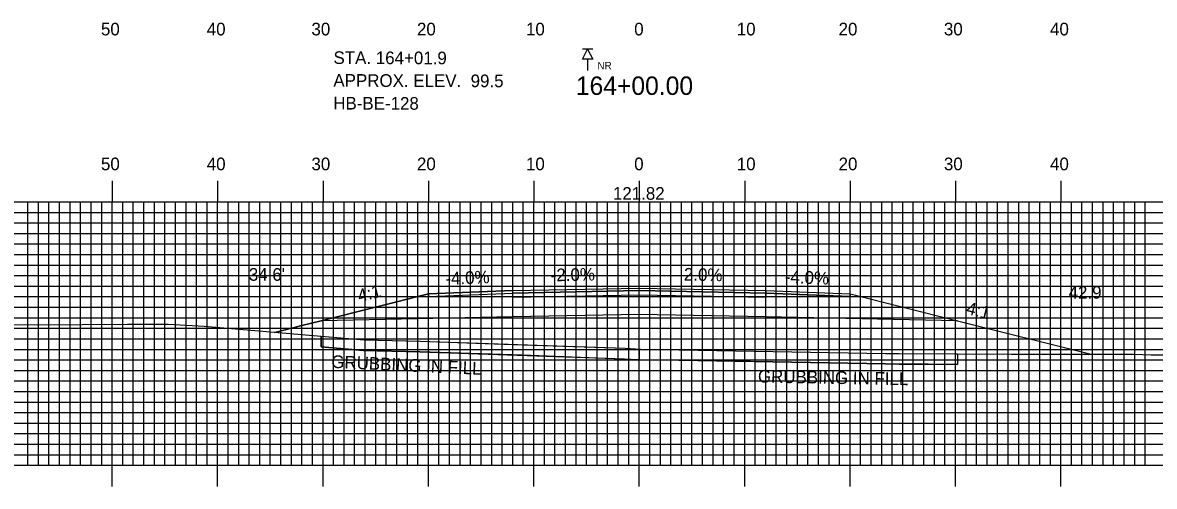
# Model space of a CAD drawing. Extents: x 1780680 to 1781023, y 442591 to 442811.
# Drawn here: x 1780786.9 to 1780894.2, y 442696.7 to 442740.7 of the extents above; entities that cross this region are included whole.
import ezdxf

# ---------------------------------------------------------------- set-up
doc = ezdxf.new("R2010")
doc.units = 0
for name, color, linetype in [('ANNOTATION', 7, 'Continuous'), ('BORING - NO REFUSAL', 7, 'Continuous'), ('D_Roadway_Centerline', 7, 'Continuous'), ('D_Roadway_Centerline_Text', 7, 'Continuous'), ('D_Roadway_Edge_Shoulder', 7, 'Continuous'), ('D_Roadway_Edge_TW', 7, 'Continuous'), ('D_Roadway_Pavement', 7, 'Continuous'), ('D_Roadway_SlopeLines', 7, 'Continuous'), ('D_Roadway_SubGrade', 7, 'Continuous'), ('D_Text_Standard', 7, 'Continuous'), ('GRUBBING IN FILL', 7, 'Continuous'), ('H_V ANNOTATION', 7, 'Continuous'), ('MAJOR', 7, 'Continuous'), ('MINOR', 7, 'Continuous'), ('S_Roadway_Centerline', 7, 'Continuous')]:
    doc.layers.add(name, color=color, linetype=linetype)

msp = doc.modelspace()

# ---------------------------------------------------------------- linework, layer by layer
at = {"layer": 'BORING - NO REFUSAL'}
for p, q in [((1780840.96, 442738.17), (1780840, 442738.17)), ((1780840.48, 442737.21), (1780840.48, 442736.15))]:
    msp.add_line(p, q, dxfattribs=at)
msp.add_lwpolyline([(1780840.48, 442738.17), (1780840.96, 442737.21), (1780840, 442737.21)], close=True, dxfattribs=at)
at = {"layer": 'D_Roadway_Centerline'}
msp.add_lwpolyline([(1780810.81, 442711.28), (1780813.38, 442711.93), (1780815.21, 442712.38), (1780825.38, 442714.93), (1780833.38, 442715.25), (1780845.38, 442715.49), (1780857.38, 442715.25), (1780865.38, 442714.93), (1780875.56, 442712.38), (1780888.25, 442709.21)], dxfattribs=at)
at = {"layer": 'D_Roadway_Edge_Shoulder'}
for points in [[(1780833.38, 442715.25), (1780825.38, 442714.93), (1780825.38, 442714.68), (1780833.38, 442715)], [(1780857.38, 442715.25), (1780865.38, 442714.93), (1780865.38, 442714.68), (1780857.38, 442715)]]:
    msp.add_lwpolyline(points, close=True, dxfattribs=at)
at = {"layer": 'D_Roadway_Edge_TW'}
msp.add_lwpolyline([(1780833.38, 442715), (1780833.38, 442715.25), (1780845.38, 442715.49), (1780857.38, 442715.25), (1780857.38, 442715), (1780845.38, 442715.24)], close=True, dxfattribs=at)
at = {"layer": 'D_Roadway_Pavement'}
msp.add_lwpolyline([(1780833.38, 442714.58), (1780833.38, 442715), (1780845.38, 442715.24), (1780857.38, 442715), (1780857.38, 442714.58), (1780845.38, 442714.82)], close=True, dxfattribs=at)
at = {"layer": 'D_Roadway_SlopeLines'}
for points in [[(1780825.38, 442714.93), (1780815.21, 442712.38), (1780813.38, 442711.93), (1780810.81, 442711.28)], [(1780865.38, 442714.93), (1780875.56, 442712.38), (1780888.25, 442709.21)]]:
    msp.add_lwpolyline(points, dxfattribs=at)
at = {"layer": 'D_Roadway_SubGrade'}
msp.add_lwpolyline([(1780833.38, 442712.75), (1780815.21, 442712.38), (1780825.38, 442714.93), (1780825.38, 442714.68), (1780833.38, 442715), (1780845.38, 442715.24), (1780857.38, 442715), (1780865.38, 442714.68), (1780865.38, 442714.93), (1780875.56, 442712.38), (1780857.38, 442712.75), (1780845.38, 442712.99)], close=True, dxfattribs=at)
at = {"layer": 'GRUBBING IN FILL'}
for p, q in [((1780815.21, 442710.91), (1780815.21, 442709.91)), ((1780815.21, 442710.91), (1780815.21, 442709.91)), ((1780875.56, 442709.24), (1780875.56, 442708.24)), ((1780875.56, 442709.24), (1780875.56, 442708.24))]:
    msp.add_line(p, q, dxfattribs=at)
for points in [[(1780815.21, 442710.91), (1780819.27, 442710.56), (1780824.58, 442710.43), (1780834.31, 442710.11), (1780844.04, 442709.78), (1780845.38, 442709.69), (1780845.38, 442708.68), (1780834.27, 442709.11), (1780824.55, 442709.43), (1780819.21, 442709.56), (1780815.21, 442709.91)], [(1780815.21, 442710.91), (1780819.27, 442710.56), (1780824.58, 442710.43), (1780834.31, 442710.11), (1780844.04, 442709.78), (1780845.38, 442709.69), (1780845.38, 442708.68), (1780834.27, 442709.11), (1780824.55, 442709.43), (1780819.21, 442709.56), (1780815.21, 442709.91)], [(1780845.38, 442709.69), (1780847.39, 442709.67), (1780858.07, 442709.48), (1780868.74, 442709.29), (1780875.56, 442709.24), (1780875.56, 442708.24), (1780872.8, 442708.26), (1780868.73, 442708.29), (1780858.05, 442708.48), (1780845.38, 442708.68)], [(1780845.38, 442709.69), (1780847.39, 442709.67), (1780858.07, 442709.48), (1780868.74, 442709.29), (1780875.56, 442709.24), (1780875.56, 442708.24), (1780872.8, 442708.26), (1780868.73, 442708.29), (1780858.05, 442708.48), (1780845.38, 442708.68)]]:
    msp.add_lwpolyline(points, close=True, dxfattribs=at)
msp.add_lwpolyline([(1780815.21, 442709.91), (1780819.21, 442709.56), (1780824.55, 442709.43), (1780843.99, 442708.78), (1780845.49, 442708.68), (1780847.37, 442708.67), (1780868.73, 442708.29), (1780870.05, 442708.27), (1780875.56, 442708.24)], dxfattribs=at)
msp.add_lwpolyline([(1780815.21, 442709.91), (1780819.21, 442709.56), (1780824.55, 442709.43), (1780843.99, 442708.78), (1780845.49, 442708.68), (1780847.37, 442708.67), (1780868.73, 442708.29), (1780870.05, 442708.27), (1780875.56, 442708.24)], dxfattribs=at)
at = {"layer": 'MAJOR'}
for p, q in [((1780795.38, 442725.67), (1780795.38, 442723.67)), ((1780805.38, 442725.67), (1780805.38, 442723.67)), ((1780815.38, 442725.67), (1780815.38, 442723.67)), ((1780825.38, 442725.67), (1780825.38, 442723.67)), ((1780835.38, 442725.67), (1780835.38, 442723.67)), ((1780845.38, 442725.67), (1780845.38, 442723.67)), ((1780855.38, 442725.67), (1780855.38, 442723.67)), ((1780865.38, 442725.67), (1780865.38, 442723.67)), ((1780875.38, 442725.67), (1780875.38, 442723.67)), ((1780885.38, 442725.67), (1780885.38, 442723.67)), ((1780705.38, 442723.67), (1780985.38, 442723.67)), ((1780705.38, 442723.67), (1780985.38, 442723.67)), ((1780795.38, 442698.67), (1780795.38, 442723.67)), ((1780805.38, 442698.67), (1780805.38, 442723.67)), ((1780815.38, 442698.67), (1780815.38, 442723.67)), ((1780825.38, 442698.67), (1780825.38, 442723.67)), ((1780835.38, 442698.67), (1780835.38, 442723.67)), ((1780845.38, 442698.67), (1780845.38, 442723.67)), ((1780855.38, 442698.67), (1780855.38, 442723.67)), ((1780865.38, 442698.67), (1780865.38, 442723.67)), ((1780875.38, 442698.67), (1780875.38, 442723.67)), ((1780885.38, 442698.67), (1780885.38, 442723.67)), ((1780705.38, 442718.67), (1780985.38, 442718.67)), ((1780705.38, 442713.67), (1780985.38, 442713.67)), ((1780705.38, 442708.67), (1780985.38, 442708.67)), ((1780705.38, 442703.67), (1780985.38, 442703.67)), ((1780705.38, 442698.67), (1780985.38, 442698.67)), ((1780705.38, 442698.67), (1780985.38, 442698.67)), ((1780795.38, 442696.66), (1780795.38, 442698.67)), ((1780805.38, 442696.66), (1780805.38, 442698.67)), ((1780815.38, 442696.66), (1780815.38, 442698.67)), ((1780825.38, 442696.66), (1780825.38, 442698.67)), ((1780835.38, 442696.66), (1780835.38, 442698.67)), ((1780845.38, 442696.66), (1780845.38, 442698.67)), ((1780855.38, 442696.66), (1780855.38, 442698.67)), ((1780865.38, 442696.66), (1780865.38, 442698.67)), ((1780875.38, 442696.66), (1780875.38, 442698.67)), ((1780885.38, 442696.66), (1780885.38, 442698.67))]:
    msp.add_line(p, q, dxfattribs=at)
at = {"layer": 'MINOR'}
for p, q in [((1780787.38, 442698.67), (1780787.38, 442723.67)), ((1780788.38, 442698.67), (1780788.38, 442723.67)), ((1780789.38, 442698.67), (1780789.38, 442723.67)), ((1780790.38, 442698.67), (1780790.38, 442723.67)), ((1780791.38, 442698.67), (1780791.38, 442723.67)), ((1780792.38, 442698.67), (1780792.38, 442723.67)), ((1780793.38, 442698.67), (1780793.38, 442723.67)), ((1780794.38, 442698.67), (1780794.38, 442723.67)), ((1780796.38, 442698.67), (1780796.38, 442723.67)), ((1780797.38, 442698.67), (1780797.38, 442723.67)), ((1780798.38, 442698.67), (1780798.38, 442723.67)), ((1780799.38, 442698.67), (1780799.38, 442723.67)), ((1780800.38, 442698.67), (1780800.38, 442723.67)), ((1780801.38, 442698.67), (1780801.38, 442723.67)), ((1780802.38, 442698.67), (1780802.38, 442723.67)), ((1780803.38, 442698.67), (1780803.38, 442723.67)), ((1780804.38, 442698.67), (1780804.38, 442723.67)), ((1780806.38, 442698.67), (1780806.38, 442723.67)), ((1780807.38, 442698.67), (1780807.38, 442723.67)), ((1780808.38, 442698.67), (1780808.38, 442723.67)), ((1780809.38, 442698.67), (1780809.38, 442723.67)), ((1780810.38, 442698.67), (1780810.38, 442723.67)), ((1780811.38, 442698.67), (1780811.38, 442723.67)), ((1780812.38, 442698.67), (1780812.38, 442723.67)), ((1780813.38, 442698.67), (1780813.38, 442723.67)), ((1780814.38, 442698.67), (1780814.38, 442723.67)), ((1780816.38, 442698.67), (1780816.38, 442723.67)), ((1780817.38, 442698.67), (1780817.38, 442723.67)), ((1780818.38, 442698.67), (1780818.38, 442723.67)), ((1780819.38, 442698.67), (1780819.38, 442723.67)), ((1780820.38, 442698.67), (1780820.38, 442723.67)), ((1780821.38, 442698.67), (1780821.38, 442723.67)), ((1780822.38, 442698.67), (1780822.38, 442723.67)), ((1780823.38, 442698.67), (1780823.38, 442723.67)), ((1780824.38, 442698.67), (1780824.38, 442723.67)), ((1780826.38, 442698.67), (1780826.38, 442723.67)), ((1780827.38, 442698.67), (1780827.38, 442723.67)), ((1780828.38, 442698.67), (1780828.38, 442723.67)), ((1780829.38, 442698.67), (1780829.38, 442723.67)), ((1780830.38, 442698.67), (1780830.38, 442723.67)), ((1780831.38, 442698.67), (1780831.38, 442723.67)), ((1780832.38, 442698.67), (1780832.38, 442723.67)), ((1780833.38, 442698.67), (1780833.38, 442723.67)), ((1780834.38, 442698.67), (1780834.38, 442723.67)), ((1780836.38, 442698.67), (1780836.38, 442723.67)), ((1780837.38, 442698.67), (1780837.38, 442723.67)), ((1780838.38, 442698.67), (1780838.38, 442723.67)), ((1780839.38, 442698.67), (1780839.38, 442723.67)), ((1780840.38, 442698.67), (1780840.38, 442723.67)), ((1780841.38, 442698.67), (1780841.38, 442723.67)), ((1780842.38, 442698.67), (1780842.38, 442723.67)), ((1780843.38, 442698.67), (1780843.38, 442723.67)), ((1780844.38, 442698.67), (1780844.38, 442723.67)), ((1780846.38, 442698.67), (1780846.38, 442723.67)), ((1780847.38, 442698.67), (1780847.38, 442723.67)), ((1780848.38, 442698.67), (1780848.38, 442723.67)), ((1780849.38, 442698.67), (1780849.38, 442723.67)), ((1780850.38, 442698.67), (1780850.38, 442723.67)), ((1780851.38, 442698.67), (1780851.38, 442723.67)), ((1780852.38, 442698.67), (1780852.38, 442723.67)), ((1780853.38, 442698.67), (1780853.38, 442723.67)), ((1780854.38, 442698.67), (1780854.38, 442723.67)), ((1780856.38, 442698.67), (1780856.38, 442723.67)), ((1780857.38, 442698.67), (1780857.38, 442723.67)), ((1780858.38, 442698.67), (1780858.38, 442723.67)), ((1780859.38, 442698.67), (1780859.38, 442723.67)), ((1780860.38, 442698.67), (1780860.38, 442723.67)), ((1780861.38, 442698.67), (1780861.38, 442723.67)), ((1780862.38, 442698.67), (1780862.38, 442723.67)), ((1780863.38, 442698.67), (1780863.38, 442723.67)), ((1780864.38, 442698.67), (1780864.38, 442723.67)), ((1780866.38, 442698.67), (1780866.38, 442723.67)), ((1780867.38, 442698.67), (1780867.38, 442723.67)), ((1780868.38, 442698.67), (1780868.38, 442723.67)), ((1780869.38, 442698.67), (1780869.38, 442723.67)), ((1780870.38, 442698.67), (1780870.38, 442723.67)), ((1780871.38, 442698.67), (1780871.38, 442723.67)), ((1780872.38, 442698.67), (1780872.38, 442723.67)), ((1780873.38, 442698.67), (1780873.38, 442723.67)), ((1780874.38, 442698.67), (1780874.38, 442723.67)), ((1780876.38, 442698.67), (1780876.38, 442723.67)), ((1780877.38, 442698.67), (1780877.38, 442723.67)), ((1780878.38, 442698.67), (1780878.38, 442723.67)), ((1780879.38, 442698.67), (1780879.38, 442723.67)), ((1780880.38, 442698.67), (1780880.38, 442723.67)), ((1780881.38, 442698.67), (1780881.38, 442723.67)), ((1780882.38, 442698.67), (1780882.38, 442723.67)), ((1780883.38, 442698.67), (1780883.38, 442723.67)), ((1780884.38, 442698.67), (1780884.38, 442723.67)), ((1780886.38, 442698.67), (1780886.38, 442723.67)), ((1780887.38, 442698.67), (1780887.38, 442723.67)), ((1780888.38, 442698.67), (1780888.38, 442723.67)), ((1780889.38, 442698.67), (1780889.38, 442723.67)), ((1780890.38, 442698.67), (1780890.38, 442723.67)), ((1780891.38, 442698.67), (1780891.38, 442723.67)), ((1780892.38, 442698.67), (1780892.38, 442723.67)), ((1780893.38, 442698.67), (1780893.38, 442723.67)), ((1780705.38, 442722.67), (1780985.38, 442722.67)), ((1780705.38, 442721.67), (1780985.38, 442721.67)), ((1780705.38, 442720.67), (1780985.38, 442720.67)), ((1780705.38, 442719.67), (1780985.38, 442719.67)), ((1780705.38, 442717.67), (1780985.38, 442717.67)), ((1780705.38, 442716.67), (1780985.38, 442716.67)), ((1780705.38, 442715.67), (1780985.38, 442715.67)), ((1780705.38, 442714.67), (1780985.38, 442714.67)), ((1780705.38, 442712.67), (1780985.38, 442712.67)), ((1780705.38, 442711.67), (1780985.38, 442711.67)), ((1780705.38, 442710.67), (1780985.38, 442710.67)), ((1780705.38, 442709.67), (1780985.38, 442709.67)), ((1780705.38, 442707.67), (1780985.38, 442707.67)), ((1780705.38, 442706.67), (1780985.38, 442706.67)), ((1780705.38, 442705.67), (1780985.38, 442705.67)), ((1780705.38, 442704.67), (1780985.38, 442704.67)), ((1780705.38, 442702.67), (1780985.38, 442702.67)), ((1780705.38, 442701.67), (1780985.38, 442701.67)), ((1780705.38, 442700.67), (1780985.38, 442700.67)), ((1780705.38, 442699.67), (1780985.38, 442699.67))]:
    msp.add_line(p, q, dxfattribs=at)
at = {"layer": 'S_Roadway_Centerline'}
msp.add_lwpolyline([(1780781.28, 442712.03), (1780788.27, 442711.98), (1780796.84, 442712.05), (1780800.7, 442712.06), (1780804.09, 442711.86), (1780819.27, 442710.56), (1780824.58, 442710.43), (1780844.04, 442709.78), (1780845.53, 442709.68), (1780847.39, 442709.67), (1780868.74, 442709.29), (1780870.05, 442709.27), (1780880.69, 442709.21), (1780892.29, 442709.21), (1780893.94, 442709.16), (1780895.49, 442709.14)], dxfattribs=at)

# ---------------------------------------------------------------- texts
at = {"layer": 'ANNOTATION'}
for s, rotation, p in [('-4.0%', 2.2906, (1780827.01, 442715.79)), ('-2.0%', 1.1458, (1780836.99, 442716.12)), ('-2.0%', 358.8542, (1780849.07, 442716.21)), ('-4.0%', 357.7094, (1780859.17, 442715.98)), ('4:1', 14.0362, (1780818.83, 442714.15)), ('4:1', 345.9638, (1780876.32, 442713.05))]:
    msp.add_text(s, height=1.2, rotation=rotation, dxfattribs=at).set_placement(p)
at = {"layer": 'BORING - NO REFUSAL'}
for s, p in [('STA. 164+01.9', (1780816.37, 442736.76)), ('APPROX. ELEV.  99.5', (1780816.36, 442734.6)), ('HB-BE-128', (1780816.35, 442732.44))]:
    msp.add_text(s, height=1.2, rotation=359.8142, dxfattribs=at).set_placement(p)
msp.add_text('NR', height=0.7, dxfattribs=at).set_placement((1780841.41, 442736.25))
at = {"layer": 'D_Roadway_Centerline'}
for s, p in [('C', (1780845.38, 442715.49)), ('L', (1780845.38, 442715.48))]:
    msp.add_text(s, height=0.0146, dxfattribs=at).set_placement(p)
at = {"layer": 'D_Roadway_Centerline_Text'}
msp.add_text('121.82', height=1.2, dxfattribs=at).set_placement((1780842.88, 442723.87))
at = {"layer": 'D_Text_Standard'}
for s, p in [("34.6'", (1780808.34, 442716.18)), ("42.9'", (1780886.11, 442714.48))]:
    msp.add_text(s, height=1.2, dxfattribs=at).set_placement(p)
at = {"layer": 'GRUBBING IN FILL'}
for rotation, p in [(357.2948, (1780816.14, 442707.92)), (358.9728, (1780856.63, 442706.52))]:
    msp.add_text('GRUBBING IN FILL', height=1.2, rotation=rotation, dxfattribs=at).set_placement(p)
at = {"layer": 'H_V ANNOTATION'}
for s, height, p in [('50', 1.2, (1780794.31, 442739.47)), ('40', 1.2, (1780804.35, 442739.47)), ('30', 1.2, (1780814.28, 442739.47)), ('20', 1.2, (1780824.29, 442739.47)), ('10', 1.2, (1780834.63, 442739.47)), ('0', 1.2, (1780844.9, 442739.47)), ('10', 1.2, (1780854.63, 442739.47)), ('20', 1.2, (1780864.29, 442739.47)), ('30', 1.2, (1780874.28, 442739.47)), ('40', 1.2, (1780884.35, 442739.47)), ('164+00.00', 1.75, (1780839.36, 442733.82)), ('50', 1.2, (1780794.31, 442726.67)), ('40', 1.2, (1780804.35, 442726.67)), ('30', 1.2, (1780814.28, 442726.67)), ('20', 1.2, (1780824.29, 442726.67)), ('10', 1.2, (1780834.63, 442726.67)), ('0', 1.2, (1780844.9, 442726.67)), ('10', 1.2, (1780854.63, 442726.67)), ('20', 1.2, (1780864.29, 442726.67)), ('30', 1.2, (1780874.28, 442726.67)), ('40', 1.2, (1780884.35, 442726.67))]:
    msp.add_text(s, height=height, dxfattribs=at).set_placement(p)

doc.saveas('drawing.dxf')
